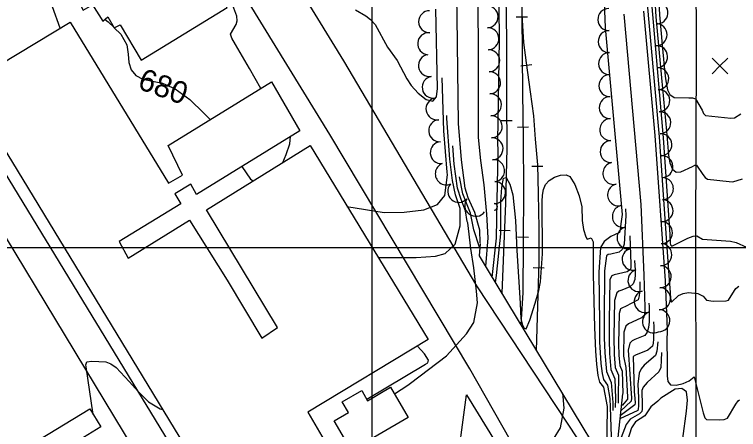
# Model space of a CAD drawing. Extents: x 79600 to 91800, y 75600 to 84400.
# Drawn here: x 83676 to 84333, y 82835 to 83212 of the extents above; entities that cross this region are included whole.
import ezdxf

# ---------------------------------------------------------------- set-up
doc = ezdxf.new("R2010")
doc.units = 0
for name, color, linetype in [('084-085$0$BLDG', 7, 'Continuous'), ('084-085$0$BRIDGE', 7, 'Continuous'), ('084-085$0$GRID', 7, 'Continuous'), ('084-085$0$INDEX', 7, 'Continuous'), ('084-085$0$INDXLBL', 7, 'Continuous'), ('084-085$0$INTER', 7, 'Continuous'), ('084-085$0$ROAD', 7, 'Continuous'), ('084-085$0$RR', 7, 'Continuous'), ('084-085$0$SPOTMARK', 7, 'Continuous'), ('084-085$0$SPOTS', 7, 'Continuous'), ('084-085$0$TREES', 7, 'Continuous'), ('084-085$0$WALL', 7, 'Continuous')]:
    doc.layers.add(name, color=color, linetype=linetype)

# ---------------------------------------------------------------- blocks, each defined once
blk = doc.blocks.new('084-085$0$RRTICK100')
blk.add_line((0, -5), (0, 5))
blk = doc.blocks.new('084-085$0$SPOTX')
at = {"layer": '084-085$0$SPOTMARK'}
for p, q in [((-0.37, 0.358), (0.351, -0.358)), ((-0.012, 0), (0.347, 0.358)), ((-0.012, 0), (-0.37, -0.358))]:
    blk.add_line(p, q, dxfattribs=at)

msp = doc.modelspace()

# ---------------------------------------------------------------- linework, layer by layer
at = {"layer": '084-085$0$BLDG'}
for points in [[(83790.49, 83170.53), (83868.55, 83218.29), (83822.21, 83291.85), (83812.61, 83286.19), (83809.63, 83290.52), (83793.84, 83280.47), (83796.82, 83274.9), (83727.74, 83234.35), (83737.81, 83215.75), (83746.48, 83220.78), (83755.75, 83205.76), (83760.39, 83209.68), (83766.05, 83199.92), (83771.47, 83202.59)], [(84051.12, 82916.57), (83941.92, 82850.43), (83967.38, 82807.06), (83872.9, 82750.02), (83630.96, 83147.76), (83726.06, 83204.95), (83815.45, 83058.75), (83828, 83065.98), (83815.08, 83092.95), (83908.93, 83150.6), (83934.71, 83106.3), (83840.7, 83048.49), (83835.67, 83057.63), (83821.11, 83048.99), (83826.6, 83040), (83770.7, 83005.6), (83778.88, 82990.42), (83834.47, 83024.97), (83868.56, 82970.61), (83899.98, 82917.95), (83914.23, 82927.53), (83849.81, 83034.4), (83944.12, 83092.99)], [(83978.76, 82850.21), (83973.14, 82859.81), (83990.75, 82870.12), (83996.08, 82861.02), (84016.94, 82873.23), (84032.98, 82845.85), (83981.53, 82815.72), (83965.79, 82842.61)], [(83753.92, 82837.15), (83706.63, 82808.26), (83703.39, 82813.57), (83697.53, 82809.99), (83690.69, 82821.19), (83743.84, 82853.66)]]:
    msp.add_lwpolyline(points, close=True, dxfattribs=at)
at = {"layer": '084-085$0$BRIDGE'}
for points in [[(84098.22, 83003.72), (84097.55, 82992.6), (84105.74, 82979.01), (84224.85, 82781.42), (84234.11, 82781.51)], [(84085.86, 82866.35), (84169.94, 82729), (84211.7, 82643.58), (84207.64, 82633.04)]]:
    msp.add_lwpolyline(points, dxfattribs=at)
at = {"layer": '084-085$0$GRID'}
for p, q in [((84000, 84000), (84000, 80000)), ((85000, 83000), (80000, 83000))]:
    msp.add_line(p, q, dxfattribs=at)
at = {"layer": '084-085$0$INDEX'}
for points in [[(84098.21, 83004.57), (84097.9, 83016.04), (84093.6, 83032.04), (84087.44, 83045.47), (84084.8, 83054.06), (84081.25, 83079.9), (84078.78, 83112.73), (84077.48, 83209.4), (84076.75, 83245.14), (84072.74, 83299.35), (84069.3, 83375.33), (84068.57, 83395), (84072.12, 83434.9), (84072.45, 83477.97), (84070.87, 83528.2), (84067.89, 83566.48), (84062.26, 83748.94), (84061.54, 83787.82), (84063.03, 83843.29), (84063.12, 83883.79), (84061.23, 83929.16)], [(84103.44, 82982.83), (84105.56, 83008.99), (84104.28, 83030.59), (84101.98, 83057.1), (84098.91, 83079.11), (84096.87, 83100.01), (84096.86, 83185.12), (84096.3, 83242.79), (84093.96, 83281.21), (84090.74, 83389.97), (84092.25, 83421.43), (84091.62, 83480.68), (84087.15, 83596.78), (84083.16, 83764.7), (84083.3, 83845.36), (84082.27, 83908.69), (84081.18, 83929.35)], [(84109.33, 82973.06), (84113.28, 83008.74), (84113.79, 83042.92), (84114.62, 83086.88), (84114.37, 83096.72), (84115.78, 83189.02), (84114.89, 83277.88)], [(84209.45, 83261.09), (84211.82, 83200.04), (84226.59, 83036.85), (84227.18, 83030.16), (84226.03, 83021.75), (84225.4, 83016.32), (84224.8, 83013.75), (84217.06, 83010.14), (84210.78, 83005.62), (84207.66, 83000.22), (84206.19, 82977.81), (84206.57, 82931.47), (84206.78, 82914.33), (84207.98, 82894.76), (84209.04, 82885.77), (84210.41, 82880.37), (84213.85, 82875.24), (84215.98, 82863.05), (84216.41, 82855.24), (84217.63, 82819.49)], [(83717.01, 83199.51), (83710.15, 83219.01), (83705.95, 83231.12), (83703.28, 83241.53), (83703.65, 83247.29), (83707.89, 83246.49), (83724.62, 83231.44), (83732.14, 83226.22)], [(83899.33, 83144.7), (83888.9, 83162.76), (83876.24, 83184.65), (83872.84, 83190.38), (83871.65, 83194.15), (83876.74, 83202.7), (83877.7, 83206.11), (83877.38, 83210.38), (83873.01, 83222.42), (83869.53, 83228.95), (83865.87, 83233.88), (83862.39, 83236.05), (83857.91, 83235.18)], [(83985.08, 83216.19), (83994.63, 83210.69), (83998.79, 83207.32), (84003.09, 83202.78), (84014.06, 83182.38), (84022.88, 83170.27), (84031.77, 83153.56), (84035.62, 83147.43), (84042, 83140.45), (84049.36, 83134.76), (84055.49, 83133.11), (84058.73, 83137.2), (84059.72, 83144.6), (84058.11, 83216.88)], [(84246.56, 83214.98), (84257.02, 83101.83), (84266.31, 82969.76), (84268.2, 82925.67), (84267.84, 82914.47), (84268.09, 82897.26), (84268.09, 82890.25), (84267.98, 82883.73), (84268.67, 82878.53), (84271.28, 82875.47), (84276.41, 82875.1), (84282.66, 82876.62), (84288.1, 82878.92), (84292.61, 82882.57), (84300.86, 82849.89), (84302.27, 82845.43), (84303.81, 82843.76), (84315.61, 82843.5), (84319.96, 82844.01), (84322.78, 82845.14), (84330.54, 82857.99), (84332.48, 82860.89), (84333.73, 82861.84)], [(84228.88, 83212.3), (84244.18, 83039.31), (84246.84, 82974.93), (84247.81, 82945.86), (84247.91, 82942.01), (84247.51, 82938.97), (84244.9, 82936.25), (84236.25, 82932.45), (84233.09, 82930.72), (84230.63, 82928.66), (84228.76, 82923.26), (84228.53, 82901.56), (84230.62, 82891.18), (84232.2, 82864.59), (84232.11, 82862.28), (84227.6, 82856.85), (84227.54, 82856.71)], [(83757.81, 83207.5), (83760.69, 83205.26), (83765.97, 83200.05)], [(83766.08, 83199.94), (83771.99, 83194.11), (83777.41, 83184.25), (83778.81, 83175.76), (83779.3, 83168.32), (83781.47, 83161.75), (83785.73, 83156.47), (83791.92, 83153.03), (83809.8, 83149.48), (83821.48, 83144.43), (83834.64, 83134.58), (83847.5, 83122.4), (83853.22, 83116.38)], [(83919.03, 83077.4), (83922.32, 83084.63), (83925.55, 83094.48), (83926.01, 83100.95)], [(83881.99, 83073.88), (83889.83, 83062.21), (83892.08, 83060.66)], [(84282.3, 82826.75), (84285.74, 82851.37), (84286.73, 82861.57), (84285.6, 82869.14), (84281.41, 82872.08), (84275.46, 82871.43), (84262.33, 82863.23), (84259.54, 82860.48), (84253.32, 82855.52), (84247.96, 82847.16), (84239.4, 82841.92), (84235.61, 82836.24), (84229.77, 82817.29)]]:
    msp.add_lwpolyline(points, dxfattribs=at)
at = {"layer": '084-085$0$INTER'}
for points in [[(84261.5, 83668.47), (84261.83, 83615.02), (84260.69, 83513.84), (84257.9, 83433), (84259.74, 83359.67), (84259.08, 83279.8), (84258.94, 83251.62), (84261.3, 83211.55), (84263.6, 83184.5), (84265.48, 83164.53), (84266.55, 83153.59), (84268.32, 83143.59), (84270.66, 83139.09), (84274.36, 83136.6), (84287.66, 83136.15), (84291.15, 83136.1), (84293.98, 83135.15), (84299.89, 83124.95), (84301.12, 83122.03), (84302.95, 83120.06), (84325.83, 83117.64), (84329.21, 83117.97), (84335.16, 83121.78)], [(84252.74, 83645.15), (84253.63, 83604.06), (84252.44, 83526.98), (84250.19, 83493.05), (84248.53, 83435.65), (84248.58, 83421.14), (84250.77, 83411.09), (84252.47, 83360.21), (84252, 83278.25), (84252.04, 83243.69), (84264.52, 83099.7), (84270.46, 83011.87), (84270.87, 83004.39), (84271.19, 83002.6), (84272.49, 83001.51), (84287.02, 83008.54), (84291.74, 83010.41), (84295.04, 83010.68), (84300.2, 83007.74), (84325.78, 83005.85), (84330.9, 83004.73), (84340.11, 83000.42)], [(84255.43, 83251.26), (84257.8, 83209.89), (84262.84, 83154.37), (84267.56, 83106.03), (84269.49, 83084.23), (84270.68, 83076.99), (84272.9, 83071.23), (84276.37, 83068.72), (84280.55, 83068.83), (84291.27, 83073.84), (84293.4, 83074.94), (84294.82, 83075.16), (84300.49, 83066.39), (84302.58, 83063.7), (84304.76, 83062.19), (84324.33, 83060.32), (84327.85, 83059.84), (84336.46, 83062.52)], [(84248.88, 83235.23), (84260.77, 83100.76), (84266.84, 83013.22), (84269.77, 82974.85), (84270.74, 82959.31), (84271.23, 82953.92), (84272.03, 82950.57), (84278.41, 82956.62), (84282.71, 82958.53), (84287.6, 82959.21), (84296.03, 82958.29), (84300.79, 82955.86), (84303.73, 82952.3), (84309.93, 82951.43), (84321.6, 82951.63), (84323.95, 82952.23), (84329.29, 82961.15), (84330.52, 82963.05), (84333.09, 82965.2)], [(83977.3, 83037.39), (84011.06, 83031.93), (84029.43, 83032.42), (84047.31, 83034.41), (84059.72, 83039.37), (84066.18, 83047.32), (84068.81, 83066.27), (84068.46, 83068.65), (84065.32, 83106.3), (84063.88, 83154.34)], [(84006.59, 82991.23), (84040.36, 82991.23), (84057.74, 82992.22), (84066.68, 82994.7), (84075.61, 83003.14), (84080.08, 83020.02), (84080.21, 83035.61), (84075.99, 83048.16), (84073.07, 83061.06), (84070.65, 83080.37), (84068.12, 83117.29), (84068.05, 83120.29)], [(84020.49, 82867.17), (84032.53, 82875.14), (84035.03, 82876.86), (84067.67, 82901.88), (84086.04, 82921.74), (84092.5, 82932.16), (84095.97, 82950.03), (84094.98, 82960.45), (84092.5, 82981.8), (84090.01, 82999.17), (84087.04, 83022.65), (84086.68, 83023.82), (84085.01, 83033.58), (84080.94, 83043.81), (84077.84, 83054.24), (84074.63, 83075.94), (84073.4, 83092.55)], [(84097.75, 83000.44), (84092.65, 83016.36), (84089.54, 83031.31), (84082.68, 83049.04), (84079.6, 83064.51)], [(84112.13, 82968.42), (84113.25, 82974.79), (84116.99, 83012.7), (84117.25, 83041.96), (84117.87, 83054.71), (84119.41, 83063.24), (84122.08, 83063.83), (84125.22, 83057.85), (84127.98, 83047.92), (84130.56, 83024.78), (84131.5, 82997.47), (84134.76, 82949.76), (84134.81, 82942.15), (84135.24, 82935.68), (84136.43, 82930.39), (84138.16, 82927), (84140.06, 82926.41), (84143.54, 82934.04), (84148.27, 82949.7), (84151.64, 82961.03), (84153.21, 82969.06), (84154.84, 82994.38), (84154.59, 83041.91), (84154.96, 83047.66), (84155.86, 83052.77), (84157.71, 83057.33), (84160.98, 83061.19), (84165.87, 83064.17), (84171.41, 83065.96), (84176.39, 83066.2), (84179.89, 83064.67), (84184.27, 83057.39), (84188.34, 83047.06), (84190.58, 83037.22), (84191.01, 83024.76), (84192.06, 83016.69), (84194.15, 83009.8), (84195.41, 83007.79), (84199.18, 83008.88), (84200.96, 83005.39), (84200.95, 82975.77), (84202.1, 82927.47), (84202.98, 82905.96), (84203.83, 82894.17), (84205.04, 82883.95), (84206.59, 82877.83), (84210.26, 82873.4), (84213.61, 82855.63), (84213.16, 82810.13)], [(84230.26, 83035.48), (84230.75, 83029.32), (84229.18, 83003.19), (84227.62, 82998.56), (84224.45, 82995.82), (84216.88, 82994.14), (84214.49, 82993.79), (84213.14, 82992.71), (84211.38, 82978.88), (84211.04, 82935.47), (84210.94, 82918.15), (84211.5, 82904.49), (84213.05, 82887.59), (84217.38, 82877.43), (84218.83, 82859.29), (84218.72, 82851.98)], [(84234.33, 83010.72), (84234.99, 82985.2), (84235.17, 82982.46), (84234.81, 82980.29), (84231.92, 82978.11), (84220.14, 82975.34), (84217.88, 82974.35), (84216.06, 82971.01), (84215.44, 82933.28), (84215.32, 82916.33), (84215.76, 82903.76), (84217.05, 82889.4), (84220.69, 82880.85), (84221.24, 82863.14), (84221, 82854.9)], [(84238.47, 82988.53), (84239.07, 82979.55), (84239.13, 82975.58), (84238.67, 82971.22), (84237.14, 82967.33), (84234.24, 82964.57), (84227.06, 82961.53), (84224.3, 82960.44), (84222.36, 82958.91), (84220.38, 82952.16), (84219.72, 82918.99), (84220.02, 82903.02), (84221.06, 82891.22), (84224, 82884.27), (84223.78, 82864.19), (84223.68, 82858.69)], [(84243.2, 82969.1), (84243.21, 82962.35), (84242.78, 82956.21), (84241.71, 82952.55), (84230.37, 82946.58), (84227.44, 82945.28), (84225.66, 82944.35), (84224.49, 82940.24), (84224.08, 82912.69), (84224.27, 82902.29), (84225.06, 82893.04), (84227.31, 82887.73), (84227.96, 82867.45)], [(84251.59, 82949.57), (84251.69, 82946.62), (84251.81, 82932.64), (84251.32, 82927.54), (84250.06, 82923.21), (84247.84, 82920.28), (84238.82, 82916.45), (84236.26, 82915.27), (84234.36, 82913.37), (84232.84, 82907), (84235.61, 82863.27), (84235.55, 82860.59), (84225.83, 82851.33)], [(84255.87, 82932.62), (84255.91, 82928.42), (84255.71, 82916.89), (84255.49, 82913.14), (84254.81, 82910.57), (84250.54, 82906.82), (84239.29, 82902.39), (84237.32, 82901.15), (84238.27, 82869.36), (84238.84, 82863.05), (84238.98, 82859.07), (84238.76, 82857.29), (84225.38, 82847.14)], [(84259.53, 82914.61), (84258.64, 82906.04), (84257.4, 82902.05), (84247.31, 82893.18), (84244.65, 82890.05), (84242.68, 82885.99), (84241.42, 82875.94), (84242.06, 82863.71), (84242.12, 82856.05), (84241.94, 82853.66), (84241.48, 82852.02), (84225.09, 82844.46)], [(83995.37, 82862.24), (83995.57, 82862.46), (84048.82, 82894.13), (84050.91, 82895.45), (84051.31, 82897.78), (84047.89, 82903.68), (84041.36, 82910.66)], [(84263, 82904.87), (84262.65, 82897.93), (84262.47, 82891.3), (84260.67, 82887.25), (84250.11, 82877.65), (84246.21, 82873.38), (84245.06, 82870.26), (84245.41, 82856.58), (84245.4, 82853.25), (84245.26, 82851.27), (84242.9, 82848.92), (84234.59, 82844.11), (84230.79, 82839.3), (84226.27, 82827.49), (84223.8, 82810.59), (84222.19, 82796.01), (84221.46, 82787.56)], [(83747.05, 82848.4), (83740.63, 82891.91), (83740.31, 82893.55), (83741.14, 82896.18), (83745.82, 82896.84), (83758.33, 82896.17), (83763.08, 82894.46), (83767.86, 82891.09), (83779.6, 82878.41), (83787.67, 82869.21), (83797.2, 82860.11), (83807.88, 82853.48), (83810.26, 82853)], [(84173.14, 82867.21), (84173.43, 82864.66), (84174.43, 82854.23), (84170.95, 82836.36), (84164.5, 82825.94), (84146.12, 82806.09), (84130.22, 82793.89)]]:
    msp.add_lwpolyline(points, dxfattribs=at)
at = {"layer": '084-085$0$ROAD'}
for points in [[(84068.32, 83940.14), (84276.69, 83941.07), (84281.64, 83939.73), (84285.05, 83938.06), (84288.78, 83935.48), (84290.2, 83933.17), (84291.63, 83928.56), (84293.37, 83659.17), (84293.22, 83470.82), (84294.55, 83180.43), (84293.92, 83010.13), (84294.06, 82855.13), (84293.55, 82734.55)], [(84218.05, 82779.24), (84095.43, 82965.45), (84054.25, 83035.07), (83974.58, 83169.83), (83937.97, 83229.77), (83934.5, 83238.14), (83932.12, 83245.43), (83930.68, 83252.42), (83930.45, 83262.99), (83930.7, 83273.88), (83930.62, 83384.42), (83934.59, 83395.48), (83936.6, 83397.21), (83939.55, 83398.62), (83939.01, 83409.97), (83934.03, 83411.18), (83931.37, 83413.34), (83929.96, 83414.89), (83930.08, 83420.18), (83928.84, 83739.98)], [(84207.45, 82681.02), (84088.92, 82889.89), (83961.78, 83102.89), (83812.86, 83345.74), (83808.8, 83347.73), (83805.69, 83347.72), (83800.26, 83346.13), (83793.13, 83342.66), (83589.31, 83218.7), (83585.91, 83214.64), (83584.54, 83211.05), (83584.57, 83205.15), (83587.1, 83198.32), (83865.97, 82740.49)], [(83820.15, 82756.99), (83559.81, 83187.58), (83557.15, 83190.67), (83556.05, 83192.06), (83553.71, 83192.98), (83551.22, 83193.12), (83546.87, 83192.31), (83542.07, 83190.26), (83492.35, 83159.63), (83372.63, 83086.42), (83333.6, 83062.85), (83330.66, 83060.35), (83329.43, 83058.32), (83328.67, 83055.36), (83328.69, 83052.25), (83331.05, 83047.45), (83609.46, 82587.59)]]:
    msp.add_lwpolyline(points, dxfattribs=at)
at = {"layer": '084-085$0$RR'}
for points in [[(84096.53, 83929.49), (84103.19, 83750.54), (84108.53, 83600.06), (84113.09, 83482.78), (84114.33, 83450.83), (84117.45, 83369.65), (84119.19, 83317.95), (84120.62, 83267.02), (84121.62, 83228.43), (84122.17, 83188.76), (84122.4, 83133.8), (84122.52, 83090.42), (84121.47, 83040.54), (84118.06, 82958.59)], [(84117.71, 83929.69), (84124.23, 83761.25), (84130.47, 83582.53), (84133.89, 83424.78), (84135.34, 83277.51), (84136.15, 83211.75), (84136.85, 83140.89), (84137.26, 83098.9), (84137.72, 83052.9), (84137.27, 83003.95), (84137.1, 82959.33), (84135.25, 82930.06)], [(84136.15, 83211.75), (84137.63, 83186.6), (84139.97, 83168.09), (84143.63, 83141.73), (84146.63, 83119.83), (84148.38, 83098.7), (84150.31, 83075.41), (84151.03, 83049.17), (84151.65, 83017.68), (84151.64, 82987.27), (84149.31, 82906.74)]]:
    msp.add_lwpolyline(points, dxfattribs=at)
at = {"layer": '084-085$0$TREES'}
for centre, radius, start, end in [((84258.9, 83213.5), 10, 265.23882, 85.23882), ((84052.44, 83205.33), 10, 90.29545, 270.29545), ((84104.63, 83209.86), 10, 272.13965, 92.13965), ((84215.2, 83207.27), 10, 90.92598, 270.92598), ((84258.09, 83193.53), 10, 270.11316, 90.11316), ((84051.6, 83185.37), 10, 84.85747, 264.85747), ((84105.38, 83189.87), 10, 272.13965, 92.13965), ((84215.52, 83187.28), 10, 90.92598, 270.92598), ((84258.58, 83173.54), 10, 272.71287, 92.71287), ((84052.3, 83165.54), 10, 99.21528, 279.21528), ((84106.13, 83169.88), 10, 272.13965, 92.13965), ((84215.85, 83167.28), 10, 90.92598, 270.92598), ((84259.53, 83153.56), 10, 272.71287, 92.71287), ((84055.69, 83145.83), 10, 100.261, 280.261), ((84106.87, 83149.9), 10, 272.13965, 92.13965), ((84216.17, 83147.28), 10, 90.92598, 270.92598), ((84260.48, 83133.59), 10, 272.71287, 92.71287), ((84059.15, 83126.13), 10, 99.71084, 279.71084), ((84107.62, 83129.91), 10, 272.13965, 92.13965), ((84216.49, 83127.28), 10, 90.92598, 270.92598), ((84261.42, 83113.61), 10, 272.71287, 92.71287), ((84061.57, 83106.3), 10, 94.17829, 274.17829), ((84108.37, 83109.93), 10, 272.13965, 92.13965), ((84216.89, 83107.29), 10, 91.33406, 271.33406), ((84262.37, 83093.63), 10, 272.71287, 92.71287), ((84063.03, 83086.35), 10, 94.17829, 274.17829), ((84109.11, 83089.94), 10, 272.13965, 92.13965), ((84217.35, 83087.29), 10, 91.33408, 271.33408), ((84263.32, 83073.65), 10, 272.71287, 92.71287), ((84110.54, 83070), 10, 276.0592, 96.0592), ((84219.74, 83067.53), 10, 102.41601, 282.41601), ((84067.58, 83067.14), 10, 112.48964, 292.48964), ((84263.77, 83053.66), 10, 269.90277, 89.90277), ((84078.85, 83051.22), 10, 138.09562, 318.09562), ((84111.37, 83050.06), 10, 268.69904, 88.69904), ((84224.04, 83048), 10, 102.41601, 282.41601), ((84094.3, 83038.56), 10, 143.23435, 323.23435), ((84263.47, 83033.67), 10, 268.37311, 88.37311), ((84111.08, 83037.12), 2.94, 268.69904, 88.69904), ((84228.34, 83028.47), 10, 102.41601, 282.41601), ((84232.64, 83008.93), 10, 102.41601, 282.41601), ((84262.9, 83013.68), 10, 268.37311, 88.37311), ((84237.23, 82989.47), 10, 104.12286, 284.12286), ((84262.34, 82993.68), 10, 268.37311, 88.37311), ((84242.52, 82970.19), 10, 106.57264, 286.57264), ((84261.77, 82973.69), 10, 268.37311, 88.37311), ((84248.22, 82951.02), 10, 106.57264, 286.57264), ((84261.2, 82953.7), 10, 268.37311, 88.37311), ((84255.71, 82932.57), 10, 117.61575, 297.61575), ((84260.63, 82933.71), 10, 268.37311, 88.37311)]:
    msp.add_arc(centre, radius, start, end, dxfattribs=at)
at = {"layer": '084-085$0$WALL'}
msp.add_line((84227.55, 82867.29), (84219.28, 82790.66), dxfattribs=at)
msp.add_lwpolyline([(84066.78, 82731.84), (84076.08, 82791.07), (84085.86, 82866.35)], dxfattribs=at)

# ---------------------------------------------------------------- block references
at = {"layer": '084-085$0$RR'}
for p, rotation in [((84136.17, 83209.71), -89.43398242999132), ((84140.29, 83165.81), -82.10278747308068), ((84122.45, 83115.69), -89.8415131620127), ((84137.15, 83109.71), -89.43373325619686), ((84150.34, 83074.1), -88.42377024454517), ((84120.44, 83015.73), -92.38793499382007), ((84137.33, 83009.72), -90.51739802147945), ((84151.48, 82981.82), -91.66242170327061)]:
    msp.add_blockref('084-085$0$RRTICK100', p, dxfattribs=dict(at, rotation=rotation))
at = {"layer": '084-085$0$SPOTS', "xscale": 20, "yscale": 20}
msp.add_blockref('084-085$0$SPOTX', (84316.34, 83165.19), dxfattribs=at)

# ---------------------------------------------------------------- texts
at = {"layer": '084-085$0$INDXLBL'}
msp.add_text('680', height=20, rotation=340.02424, dxfattribs=at).set_placement((83786.34, 83144.88))

doc.saveas('drawing.dxf')
